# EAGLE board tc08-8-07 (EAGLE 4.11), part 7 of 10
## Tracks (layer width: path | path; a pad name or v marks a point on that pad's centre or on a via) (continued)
MKT\  (via drill 0.61)
  Top 0.254: v203.24,152.71 201.97,153.98 201.97,158.1 B13.T2 | v243.88,153.98 244.19,154.29 244.19,156.2 243.88,156.52 243.88,159.37 245.46,160.96 245.46,164.14 245.78,164.45 B10.R1 | v240.7,84.44 240.7,71.43 241.02,71.11 241.02,66.66 241.65,66.03 241.65,55.55 242.61,54.6 D10.H2 | v198.16,86.03 197.2,86.98 197.2,96.83 196.57,97.46 196.57,106.35 195.62,107.3 C14.N1 | v197.52,152.71 196.57,152.71 196.57,153.02 194.66,154.93 v194.66,156.52 | v160.69,157.15 159.1,157.15 159.1,139.69 162.28,136.51 162.28,120 v163.23,119.05
  Route15 0.254: v210.54,150.17 208.63,152.07 B13.V1
  Bottom 0.254: B13.V1 207.36,152.71 v203.24,152.71 202.92,152.39 202.92,151.12 200.38,151.12 198.79,152.71 v197.52,152.71 | v243.88,153.98 243.56,153.66 238.8,153.66 234.67,149.53 218.48,149.53 218.16,149.85 210.86,149.85 v210.54,150.17 | v240.7,84.44 240.38,84.76 229.59,84.76 229.27,84.44 225.78,84.44 224.51,85.71 213.4,85.71 212.76,85.08 212.13,85.08 210.86,86.35 198.47,86.35 v198.16,86.03 | v194.66,156.52 194.35,156.83 190.54,156.83 189.9,156.2 187.04,156.2 186.41,156.83 177.84,156.83 177.2,156.2 174.34,156.2 173.39,157.15 v160.69,157.15 | v163.23,119.05 163.55,118.73 168.95,118.73 178.47,109.21 185.77,109.21 188.31,106.67 193.71,106.67 194.66,107.62 C14.N1
MKTK  (via drill 0.61)
  Top 0.254: v65.12,235.26 67.03,237.16 67.03,241.92 v71.79,246.68 | v70.52,247.96 69.57,248.91 v69.57,256.21 | v90.84,260.97 91.79,261.93 91.79,265.42 v91.48,265.74 | v147.04,265.1 152.12,270.18 152.12,271.45 158.79,278.12 v168.63,278.12 | v176.57,275.9 177.84,275.9 179.11,274.62 183.23,274.62 v183.23,275.9 | v264.2,256.21 263.88,255.89 263.88,253.35 265.15,252.08 v266.74,252.08 | v264.83,239.7 264.83,235.57 A08.R2
  Route2 0.254: v62.27,237.8 64.81,235.26 v65.12,235.26 | v168.63,278.12 173.71,273.04 v176.57,275.9
  Route15 0.254: v131.16,264.15 133.7,264.15 v134.66,265.1 | v183.23,275.9 184.19,275.9 185.14,274.94 191.49,274.94 191.81,274.62 217.21,274.62 220.06,271.77 222.6,271.77 224.51,273.67 226.41,271.77 235.94,271.77 237.53,273.36 239.11,271.77 249.91,271.77 262.61,259.07 262.61,258.43 263.24,257.8 263.24,257.16 v264.2,256.21 | v266.74,252.08 266.74,244.78 263.24,241.29 v264.83,239.7
  Bottom 0.254: v62.27,237.8 59.41,237.8 A25.P1 | v70.52,247.96 v71.79,246.68 | v69.57,256.21 69.25,255.89 61.63,255.89 61,256.53 60.04,256.53 59.41,255.89 58.14,255.89 57.5,256.53 57.5,259.07 74.01,259.07 74.33,258.75 76.55,258.75 76.87,259.07 88.94,259.07 v90.84,260.97 | v91.48,265.74 91.79,265.42 128.62,265.42 129.89,264.15 v131.16,264.15 | v134.66,265.1 134.97,264.78 146.72,264.78 v147.04,265.1
MKTK\  (via drill 0.61)
  Top 0.254: v277.53,209.54 276.26,210.81 276.26,226.68 268.32,234.62 A08.P2 | B04.B1 v322.3,208.9 | v257.21,239.7 257.21,244.78 256.58,245.42 256.58,249.54 255.94,250.18 A09.K2
  Bottom 0.254: v322.3,208.9 321.98,209.22 277.85,209.22 v277.53,209.54 | v257.21,239.7 257.53,239.38 263.88,239.38 264.83,238.43 267.69,238.43 A08.P2
MOVE\  (via drill 0.61)
  Top 0.254: v279.44,52.06 279.12,51.74 279.12,23.16 279.75,22.53 279.75,19.67 280.39,19.04 280.39,10.15 280.71,9.83 v280.71,5.7 | v4.48,36.5 4.8,36.82 4.8,72.38 3.53,73.65 3.53,222.24 4.16,222.87 4.16,249.23 2.89,250.49 2.89,267.32 3.53,267.96 3.53,287.64 2.58,288.6 2.58,289.23 v5.12,291.77 | v269.28,294.94 258.8,294.94 258.8,276.53 v257.85,275.58
  Route2 0.254: v257.85,275.58 259.12,274.31 261.97,274.31 265.78,270.5 260.7,265.42 259.43,265.42 256.26,262.24 254.67,262.24 253.08,260.66 A09.F2
  Bottom 0.254: v279.44,52.06 280.07,52.69 285.47,52.69 285.47,57.77 284.83,58.41 284.52,58.41 284.52,62.85 D07.D1 | v280.71,5.7 261.34,5.7 260.07,4.43 231.81,4.43 229.91,6.34 223.87,6.34 223.24,5.7 35.28,5.7 v4.48,36.5 | v5.12,291.77 5.43,291.45 52.42,291.45 53.06,290.82 55.92,290.82 56.87,289.86 61.95,289.86 62.58,289.23 82.27,289.23 83.54,290.5 96.87,290.5 97.51,289.86 130.85,289.86 132.43,291.45 143.86,291.45 144.18,291.13 181.65,291.13 182.92,292.41 202.6,292.41 202.92,292.09 206.73,292.09 207.05,292.41 209.59,292.41 211.49,294.31 229.91,294.31 230.86,293.36 234.99,293.36 235.62,293.99 268.01,293.99 268.96,294.94 v269.28,294.94
MR00  (via drill 0.61)
  Top 0.254: v57.82,267 57.5,267.32 57.5,280.02 58.14,280.66 v58.14,292.09 | v139.42,296.22 139.42,278.12 139.1,277.8 139.1,273.99 139.74,273.36 139.74,264.78 139.42,264.47 139.42,237.48 140.37,236.52 140.37,232.71 140.05,232.4 140.05,207 139.74,206.68 139.74,206.05 v141.96,203.82 | v165.14,202.24 165.14,197.15 167.99,194.3 167.99,192.71 167.04,191.76 v167.04,191.44 | v188,192.71 187.68,192.39 187.68,187.31 | 187.68,187.31 187.68,181.92 v188.31,181.28 | v192.44,196.52 190.85,194.93 190.85,190.49 187.68,187.31
  Route2 0.254: v192.44,196.52 v198.47,202.55
  Route15 0.254: v188.31,181.28 191.49,178.11 191.49,175.56 191.81,175.25 B14.M2 | v261.02,184.46 271.82,173.66 271.82,173.02 276.26,168.58 280.39,168.58 B07.P2 | v249.27,183.18 248.96,183.18 246.73,185.41 237.53,185.41 237.21,185.73 236.26,185.73 229.27,192.71 226.73,192.71 v224.19,195.25 | v207.68,194.61 207.05,194.61 201.97,199.7 201.33,199.7 v198.47,202.55
  Bottom 0.254: v57.82,267 56.23,267 A25.D1 | v58.14,292.09 58.46,291.77 81.95,291.77 82.59,292.41 97.51,292.41 98.78,293.68 101.95,293.68 102.59,293.04 129.26,293.04 130.85,294.63 131.16,294.63 133.07,296.53 139.1,296.53 v139.42,296.22 | v141.96,203.82 143.86,201.92 164.82,201.92 v165.14,202.24 | v167.04,191.44 167.36,191.76 176.88,191.76 177.52,192.39 187.68,192.39 v188,192.71 | v261.02,184.46 259.43,182.87 249.59,182.87 v249.27,183.18 | v224.19,195.25 223.24,196.2 221.97,196.2 220.7,194.93 208,194.93 v207.68,194.61
MR00\  (via drill 0.61)
  Top 0.254: v282.61,175.56 282.61,174.3 279.12,170.8 279.12,166.68 278.17,165.72 B07.R2 | v294.36,177.15 v293.09,178.42 | v305.47,176.83 307.06,178.42 307.06,179.69 v308.33,180.96 | v328.97,193.03 328.65,193.34 v328.65,195.25 | v337.54,195.25 336.9,194.61 336.9,188.9 337.86,187.95 B03.H1
  Route2 0.254: v308.33,180.96 309.6,180.96 v315.63,186.99
  Bottom 0.254: v282.61,175.56 283.56,176.52 291.18,176.52 v293.09,178.42 | v294.36,177.15 294.99,176.52 305.15,176.52 v305.47,176.83 | v315.63,186.99 317.85,189.22 322.93,189.22 326.74,193.03 v328.97,193.03 | v328.65,195.25 328.97,195.57 337.22,195.57 v337.54,195.25
MR01  (via drill 0.61)
  Top 0.254: v6.39,252.4 7.02,251.77 7.02,251.13 7.34,250.81 7.34,180.64 6.7,180.01 6.7,178.74 7.34,178.11 7.34,77.14 6.7,76.5 6.7,75.24 7.97,73.97 7.97,4.75 v7.66,4.43 | v300.07,2.21 304.84,6.97 304.84,20.94 304.2,21.58 304.2,24.44 304.52,24.75 304.52,31.1 305.15,31.74 305.15,56.5 307.69,59.04 307.69,62.53 307.38,62.85 307.38,64.76 308.65,66.03 308.65,68.88 308.01,69.52 v308.01,75.87 | v281.34,76.19 281.66,76.5 281.66,88.89 v280.71,89.84 | v273.4,90.16 273.4,97.46 v273.09,97.78 | v280.71,101.27 280.71,104.13 C07.P2 280.71,105.4 v280.71,109.52 | v242.61,109.52 242.92,109.21 v242.92,106.67
  Route2 0.254: v278.17,98.73 v280.71,101.27
  Route15 0.254: v243.24,113.33 232.45,124.13 232.45,125.4 221.33,136.51 221.33,137.78 221.02,138.1 221.02,139.05 C12.B1 | v255.31,107.62 v252.77,105.08 | v280.71,109.52 v277.85,112.38
  Bottom 0.254: v6.39,252.4 15.59,261.61 47.98,261.61 48.61,262.24 57.19,262.24 58.14,263.19 A25.E1 | v7.66,4.43 7.97,4.12 8.61,4.12 8.93,3.8 9.88,3.8 11.15,2.53 228,2.53 228.64,3.16 229.27,3.16 230.54,1.89 261.66,1.89 262.93,3.16 263.56,3.16 265.47,1.26 299.12,1.26 v300.07,2.21 | v308.01,75.87 307.69,75.55 282.61,75.55 281.98,76.19 v281.34,76.19 | v280.71,89.84 280.39,90.16 v273.4,90.16 | v273.09,97.78 273.72,97.14 276.58,97.14 v278.17,98.73 | v243.24,113.33 241.65,111.75 241.65,109.52 v242.61,109.52 | v242.92,106.67 246.1,103.49 251.18,103.49 v252.77,105.08 | v255.31,107.62 257.53,109.84 264.2,109.84 264.83,110.48 267.05,110.48 267.69,109.84 275.31,109.84 v277.85,112.38
MR01\  (via drill 0.61)
  Top 0.254: v302.61,123.49 301.98,124.13 301.98,134.29 v302.61,134.93 | v254.04,129.21 255.62,127.62 255.62,125.72 254.35,124.45 254.35,122.54 255.94,120.96 v255.94,119.37
  Route2 0.254: v284.2,110.16 278.48,104.44 278.48,102.86 278.17,102.54 278.17,102.22 C07.R2 | v302.61,123.49 v293.72,114.61 | v302.61,134.93 302.93,134.93 306.42,138.42 306.42,139.05 309.6,142.23 310.23,142.23 312.14,144.13 313.73,144.13 320.39,150.8 320.39,153.02 320.71,153.34 320.71,154.29 324.52,158.1 324.52,159.05 336.27,170.8 336.27,172.39 337.86,173.98 B03.M1 | v217.21,171.44 210.86,177.79 210.86,178.11 203.55,185.41 203.55,187.95 204.82,189.22 198.79,195.25 198.79,199.38 B14.C1
  Route15 0.254: v217.21,171.44 217.21,170.49 221.97,165.72 221.97,159.37 230.22,151.12 230.22,150.8 230.86,150.17 231.81,150.17 242.29,139.69 243.56,139.69 v254.04,129.21 | v259.12,117.78 259.12,116.51 260.7,114.92 261.66,114.92 263.24,113.33 263.24,112.7 266.1,109.84 266.1,108.89 269.59,105.4 269.59,104.76 271.5,102.86 276.26,102.86 277.21,101.91 C07.R2
  Bottom 0.254: v284.2,110.16 284.52,109.84 288.96,109.84 v293.72,114.61 | v255.94,119.37 257.53,117.78 v259.12,117.78
N$1
  Bottom 0.254: B08.S2 268.96,162.23 269.91,163.18 289.28,163.18 290.23,162.23 293.09,162.23 B06.S2
N$2
  Top 0.254: C16.M2 166.41,111.75 166.41,116.83 C16.K2 | C16.N2 163.23,108.57 163.23,113.65 C16.L2 163.23,114.92 163.23,115.24 161.64,116.83 161.64,131.75 157.52,135.88 157.52,139.05 C17.B1
  Bottom 0.254: C16.K2 166.41,116.83 164.18,114.61 C16.L2
N$3  (via drill 0.61)
  Top 0.254: v230.54,166.04 230.54,162.55 B11.S2 | v239.43,175.56 239.11,175.88 239.11,176.52 238.48,177.15 238.48,188.27 v239.11,188.9 | v243.88,207.95 243.88,220.65 243.56,220.97 243.56,222.87 243.24,223.19 243.24,223.83 244.51,225.09 v244.51,226.05 | v233.72,230.49 233.72,234.3 A11.R1
  Route2 0.254: v230.54,166.04 236.89,172.39 236.89,173.02 v239.43,175.56 | v239.11,188.9 236.57,191.44 244.51,199.38 244.51,207.31 v243.88,207.95
  Route15 0.254: v244.51,226.05 v240.38,230.18
  Bottom 0.254: v240.38,230.18 240.07,230.49 v233.72,230.49
N$4
  Top 0.254: D13.S2 204.19,28.88 201.97,31.1 D13.R2
N$5  (via drill 0.61)
  Top 0.254: v15.91,149.85 15.59,150.17 15.59,209.54 12.42,212.71 12.42,246.05 15.59,249.23 15.59,274.31 v34.96,293.68 | v65.44,296.22 77.51,296.22 87.03,286.69 87.03,275.26 92.43,269.86 92.43,264.78 v93.38,263.83 | v159.42,261.29 162.6,261.29 162.91,261.61 166.41,261.61 166.41,257.8 A16.H2
  Route15 0.254: v160.69,89.21 156.56,85.08 151.48,90.16 150.21,90.16 v149.26,89.21
  Bottom 0.254: v160.69,89.21 162.91,89.21 C16.V2 | v149.26,89.21 146.09,89.21 145.13,90.16 62.58,90.16 13.05,139.69 13.05,149.85 v15.91,149.85 | v34.96,293.68 38.14,296.85 64.81,296.85 v65.44,296.22 | v93.38,263.83 98.14,259.07 152.12,259.07 154.66,261.61 159.1,261.61 v159.42,261.29
N$6
  Top 0.254: D12.C1 223.56,67.3 223.56,72.38 D12.A1 | D12.B1 220.38,69.2 220.38,64.12 D12.D1
  Bottom 0.254: D12.B1 221.33,70.16 223.56,72.38 D12.A1 | D13.F2 202.28,57.46 203.87,59.04 206.73,59.04 209.27,61.58 218.48,61.58 220.06,63.17 D12.D1
N$7
  Top 0.254: A12.P1 223.24,238.43 221.02,240.65 A12.N1 220.38,241.92 220.38,242.24 219.43,243.19 219.43,252.4 220.38,253.35 A12.J1
N$8
  Top 0.254: D17.F2 150.53,57.77 148.94,59.36 148.94,75.55 149.26,75.87 149.26,84.44 154.34,89.52 154.34,90.47 155.61,91.74 155.61,96.83 157.2,98.41 C17.R1
N$10  (via drill 0.61)
  Top 0.254: v233.72,141.27 233.08,141.91 v233.08,150.48 | v215.3,154.61 215.62,154.93 215.62,167.31 v215.3,167.63 | v223.56,171.12 223.56,173.98 B12.M1
  Route2 0.254: v221.02,168.58 v223.56,171.12
  Bottom 0.254: v233.72,141.27 234.67,141.27 234.67,139.69 236.26,138.1 236.26,137.15 C11.C1 | v233.08,150.48 232.76,150.17 223.56,150.17 222.29,151.43 221.65,151.43 221.33,151.12 218.79,151.12 v215.3,154.61 | v215.3,167.63 215.94,166.99 219.43,166.99 v221.02,168.58
N$11  (via drill 0.61)
  Top 0.254: v233.72,129.21 233.72,127.62 C11.F1 | v241.02,131.43 241.34,131.75 241.34,138.42 242.61,139.69 v242.61,140.64 | v245.78,141.27 245.46,141.59 245.46,150.48 v245.78,150.8 | v221.02,154.29 219.75,155.56 219.75,157.79 219.11,158.42 219.11,160.64 220.38,161.91 220.38,164.45 B12.R1
  Bottom 0.254: v233.72,129.21 235.94,131.43 v241.02,131.43 | v242.61,140.64 243.24,141.27 v245.78,141.27 | v245.78,150.8 244.83,151.75 244.83,156.83 241.34,156.83 239.43,154.93 237.84,154.93 237.21,154.29 225.78,154.29 225.46,154.61 224.83,154.61 224.51,154.29 v221.02,154.29
N$12
  Top 0.254: D17.E2 153.39,60.63 151.17,62.85 D17.D2
N$13
  Top 0.254: A14.K2 191.81,251.45 191.81,256.53 A14.H2 | B15.F1 182.92,191.12 183.87,192.08 183.87,208.58 183.23,209.22 183.23,220.02 187.04,223.83 187.04,248.91 187.68,249.54 187.68,252.4 188.63,253.35 A14.J2
  Bottom 0.254: A14.H2 191.81,256.53 189.58,254.3 A14.J2
N$14
  Top 0.254: A16.E2 166.09,263.83 163.87,266.05 A16.D2
N$15  (via drill 0.61)
  Top 0.254: v135.29,138.42 v135.29,140.96 | v113.07,142.55 112.43,143.18 v112.43,149.53 | v43.22,148.26 41.63,149.85 41.63,178.42 41.95,178.74 41.95,183.18 41.63,183.5 41.63,204.14 42.26,204.77 v42.26,214.62 | v17.82,223.83 16.23,223.83 16.23,235.57 16.55,235.89 16.55,240.33 16.23,240.65 16.23,273.67 v36.23,293.68 | v104.18,295.58 120.69,279.07 129.89,279.07 129.89,270.5 130.53,269.86 130.53,266.05 132.12,264.47 v132.12,262.56
  Route2 0.254: v113.07,142.55 v115.61,140.01
  Route15 0.254: v154.98,139.37 157.52,136.83 159.74,136.83 C17.C1
  Bottom 0.254: v154.98,139.37 153.39,140.96 v135.29,140.96 | v135.29,138.42 117.19,138.42 v115.61,140.01 | v112.43,149.53 111.8,148.89 81.95,148.89 80.68,147.62 58.77,147.62 58.14,148.26 v43.22,148.26 | v42.26,214.62 35.6,221.29 33.06,221.29 30.83,223.51 18.13,223.51 v17.82,223.83 | v36.23,293.68 36.55,293.99 52.74,293.99 53.06,294.31 64.17,294.31 64.49,293.99 81.32,293.99 82.27,294.94 97.19,294.94 97.83,295.58 v104.18,295.58 | v132.12,262.56 133.07,261.61 142.91,261.61 143.55,262.24 161.33,262.24 162.91,260.66 A16.F2
N$16  (via drill 0.61)
  Top 0.254: v152.12,209.54 152.12,139.05 151.8,138.74 151.8,134.61 151.17,133.97 C17.D2 | v178.79,209.54 178.47,209.86 178.47,224.46 178.15,224.78 178.15,241.29 180.69,243.83 180.69,261.61 181.33,262.24 181.33,265.1 182.28,266.05 A15.D1 183.23,267 185.46,269.23 A15.C1
  Bottom 0.254: v152.12,209.54 v178.79,209.54
N$17  (via drill 0.61)
  Top 0.254: v182.92,137.78 182.92,137.15 181.33,135.56 181.33,130.16 178.15,126.99 178.15,121.91 177.52,121.27 177.52,88.25 177.2,87.94 177.2,71.43 177.52,71.11 177.52,69.2 177.2,68.88 177.2,64.76 176.57,64.12 D15.D2 | v185.46,139.69 187.04,141.27 187.04,160.64 v188,161.59 | v192.44,171.12 190.85,169.53 190.85,166.36 192.12,165.09 B14.S2
  Bottom 0.254: v182.92,137.78 184.82,139.69 v185.46,139.69 | v188,161.59 191.49,161.59 B14.S2 | v192.44,171.12 194.66,171.12 B14.N1
N$18  (via drill 0.61)
  Top 0.254: v189.27,192.08 190.22,193.03 190.22,207 190.85,207.63 190.85,236.52 191.81,237.48 A14.P2 191.49,238.43 189.27,240.65 A14.N2 189.58,241.61 191.81,243.83 A14.M2
  Bottom 0.254: v189.27,192.08 188.95,191.76 177.84,191.76 176.88,190.8 B15.F2
N$19
  Top 0.254: A14.L2 189.58,247.96 194.03,247.96 194.03,250.81 198.16,254.94 198.16,256.53 A14.H1
N$20
  Top 0.254: A16.S2 166.09,232.08 163.87,234.3 A16.R2
N$21
  Top 0.254: A14.E2 191.49,263.83 189.27,266.05 A14.D2
N$22  (via drill 0.61)
  Top 0.254: v229.91,230.18 229.91,226.05 A11.U2
  Bottom 0.254: v229.91,230.18 220.38,230.18 220.06,229.86 197.52,229.86 197.2,230.18 194.98,230.18 194.66,229.86 190.54,229.86 189.58,228.9 A14.T2
N$23  (via drill 0.61)
  Top 0.254: v188.95,236.52 187.68,237.8 187.68,248.27 190.22,250.81 190.22,254.62 189.58,255.26 189.58,259.38 189.27,259.7 A14.F2
  Bottom 0.254: v188.95,236.52 189.27,236.21 225.78,236.21 227.68,238.11 A11.P2
N$24  (via drill 0.61)
  Top 0.254: v172.44,108.89 171.8,108.25 171.8,104.13 172.12,103.81 172.12,99.68 172.76,99.05 C16.S1 | v105.13,115.56 105.13,172.07 v106.72,173.66 | v163.23,174.3 166.41,177.47 166.41,180.33 B16.K2
  Route15 0.254: v172.44,108.89 172.44,109.21 v168.31,113.33
  Bottom 0.254: v168.31,113.33 167.99,113.02 131.16,113.02 128.62,115.56 v105.13,115.56 | v106.72,173.66 108.94,175.88 124.5,175.88 124.81,176.2 130.85,176.2 131.16,176.52 136.56,176.52 137.2,175.88 149.26,175.88 151.8,173.34 162.28,173.34 v163.23,174.3
N$25
  Top 0.254: A14.V2 188.63,222.87 187.68,223.83 187.68,233.35 188.63,234.3 A14.R2
N$26
  Bottom 0.254: A14.S2 192.76,231.45 197.84,231.45 A14.S1
N$27
  Top 0.254: D15.S2 179.11,29.2 177.52,30.78 177.52,33.32 176.57,34.28 176.57,37.45 D15.N2
N$28  (via drill 0.61)
  Top 0.254: v224.19,84.76 224.19,91.43 C12.U1 | v246.42,78.09 246.1,77.77 246.1,73.97 v246.42,73.65 | v245.78,61.9 246.42,61.27 246.42,58.72 247.37,57.77 247.37,53.96 244.83,51.42 244.83,42.21 245.78,41.26 v245.78,39.68 | v214.67,34.6 212.44,34.6 212.44,33.01 209.9,30.47 v209.9,17.45 | v129.89,17.45 127.35,19.99 127.35,99.68 127.67,100 127.67,103.81 127.35,104.13 127.35,121.59 v127.99,122.22 | v125.45,141.27 125.77,141.59 125.77,150.17 124.18,151.75 124.18,174.3 v125.13,175.25 | v127.35,177.47 v127.35,182.23 | v168.95,181.92 168.63,182.23 168.63,185.41 v170.22,186.99
  Route2 0.254: v246.42,73.65 245.46,72.69 245.46,71.11 244.83,70.47 244.83,62.85 v245.78,61.9 | v125.13,175.25 v127.35,177.47
  Route15 0.254: v193.08,189.54 194.35,189.54 197.84,186.04 203.24,186.04 205.78,183.5 206.73,183.5 207.36,182.87 208.63,182.87 209.27,182.23 209.27,180.96 210.54,179.69 212.13,179.69 213.71,178.11 B12.L2
  Bottom 0.254: v224.19,84.76 224.19,84.13 226.1,82.22 226.1,80.32 244.19,80.32 v246.42,78.09 | v245.78,39.68 244.83,38.72 242.29,38.72 240.38,36.82 239.11,36.82 238.16,37.77 234.99,37.77 234.03,36.82 217.21,36.82 214.98,34.6 v214.67,34.6 | v209.9,17.45 209.59,17.13 182.28,17.13 181.65,17.77 177.84,17.77 177.2,17.13 130.21,17.13 v129.89,17.45 | v127.99,122.22 121.32,128.89 115.29,128.89 114.65,129.53 114.65,140.96 125.13,140.96 v125.45,141.27 | v127.35,182.23 168.63,182.23 v168.95,181.92 | v170.22,186.99 172.44,189.22 176.88,189.22 177.52,189.85 181.33,189.85 181.96,189.22 192.76,189.22 v193.08,189.54
N$29
  Top 0.254: B16.D2 163.87,196.2 166.09,193.98 B16.E2
N$30  (via drill 0.61)
  Top 0.254: v153.39,119.37 152.75,120 152.75,128.58 153.71,129.53 C17.E2 | v120.69,120.96 120.37,121.27 v120.37,188.58
  Bottom 0.254: v153.39,119.37 152.75,118.73 122.91,118.73 v120.69,120.96 | v120.37,188.58 158.47,188.58 160.06,190.17 162.91,190.17 B16.F2
N$31  (via drill 0.61)
  Top 0.254: v153.71,259.38 148.94,254.62 148.94,221.29 149.26,220.97 149.26,211.44 148.94,211.12 148.94,129.21 150.53,127.62 C17.F2
  Bottom 0.254: v153.71,259.38 154.02,259.07 165.45,259.07 168.31,261.93 174.66,261.93 175.93,263.19 | 175.93,263.19 178.79,263.19 A15.E2 | 175.93,263.19 175.93,266.05 A15.D2
N$32  (via drill 0.61)
  Top 0.254: v132.12,115.88 130.53,117.46 130.53,149.21 131.16,149.85 v131.16,150.17 | v181.01,155.24 v181.01,161.59
  Bottom 0.254: v132.12,115.88 132.43,115.56 151.48,115.56 152.75,114.29 C17.L1 | v131.16,150.17 137.51,150.17 138.15,150.8 144.82,150.8 145.45,150.17 156.88,150.17 160.37,153.66 166.41,153.66 167.04,154.29 176.57,154.29 177.2,154.93 178.15,154.93 178.79,154.29 180.06,154.29 v181.01,155.24 | v181.01,161.59 185.14,161.59 B15.S1
N$33  (via drill 0.61)
  Top 0.254: v261.34,164.77 263.24,166.68 263.24,183.5 v262.93,183.82 | v252.77,192.08 250.86,193.98 v250.86,196.2 | v256.58,197.47 257.53,198.43 v257.53,205.41 | v264.2,206.68 264.2,221.29 263.88,221.6 263.88,222.87 266.1,225.09 267.69,225.09 A08.U2
  Route2 0.254: v259.75,163.18 v261.34,164.77
  Bottom 0.254: v259.75,163.18 250.86,163.18 249.91,162.23 B10.S1 | v262.93,183.82 262.93,186.36 263.24,186.68 263.24,189.54 261.66,189.54 261.34,189.85 260.07,189.85 259.43,189.22 251.81,189.22 251.18,189.85 251.18,192.08 v252.77,192.08 | v250.86,196.2 251.5,195.57 254.67,195.57 v256.58,197.47 | v257.53,205.41 257.85,205.09 262.61,205.09 v264.2,206.68
N$34  (via drill 0.61)
  Top 0.254: v146.4,27.29 145.77,27.93 145.77,73.33 148.63,76.19 148.63,84.76 152.75,88.89 152.75,96.83 153.71,97.78 C17.S2
  Bottom 0.254: v146.4,27.29 149.58,27.29 149.9,26.98 161.64,26.98 162.91,25.71 D16.T2
N$35  (via drill 0.61)
  Top 0.254: v283.25,239.38 282.93,239.7 282.93,249.54 v283.25,249.86
  Route2 0.254: v248.96,108.89 245.15,105.08 243.56,105.08 C10.P2 | v202.6,163.5 203.24,163.5 207.36,167.63 208.63,167.63 210.54,169.53 216.57,169.53 220.7,173.66 220.7,175.88 221.97,177.15 221.97,192.39 221.02,193.34 221.97,194.3 222.6,194.3 223.24,194.93 223.24,195.57 v224.19,196.52 | v236.89,189.85 239.11,187.63 241.02,189.54 241.02,192.08 239.75,193.34 240.7,194.3 241.65,194.3 242.29,194.93 243.24,194.93 244.83,196.52 244.83,197.47 255.31,207.95 257.85,207.95 260.7,210.81 260.7,213.67 264.2,217.16 264.2,219.38 274.04,229.22 274.04,229.54 274.99,230.49 275.31,230.49 282.29,237.48 282.29,238.43 v283.25,239.38 | v271.82,256.21 271.82,257.48 269.28,260.02 268.96,259.7 267.69,259.7 263.88,263.51 262.61,262.24 261.02,262.24 259.43,260.66 A09.F1
  Route15 0.254: v248.96,108.89 245.46,112.38 245.46,113.02 244.83,113.65 244.83,119.05 244.19,119.69 244.19,120.64 241.65,123.18 241.65,123.81 241.02,124.45 240.38,124.45 225.78,139.05 225.78,143.81 217.21,152.39 216.25,152.39 207.36,161.28 207.05,161.28 206.41,161.91 206.41,162.86 204.82,164.45 204.19,164.45 202.92,163.18 v202.6,163.5 | v224.19,196.52 225.46,196.52 226.41,195.57 230.22,195.57 231.49,194.3 231.49,193.66 233.08,192.08 234.67,192.08 v236.89,189.85
  Bottom 0.254: v283.25,249.86 282.93,249.54 279.44,249.54 272.77,256.21 v271.82,256.21
N$36  (via drill 0.61)
  Top 0.254: v198.79,109.21 198.79,105.4 C14.P1 | v203.87,109.52 203.55,109.84 203.55,133.34 204.19,133.97 204.19,134.61 203.55,135.24 201.97,135.24 201.97,133.97 C13.D2
  Bottom 0.254: v198.79,109.21 199.11,109.52 v203.87,109.52
N$37
  Top 0.254: B16.S2 166.09,162.23 163.87,164.45 B16.R2
N$38
  Top 0.254: C15.H1 186.09,124.45 187.04,125.4 187.04,133.02 186.09,133.97 186.09,135.88 C15.C1
N$39
  Top 0.254: C15.J1 182.28,121.27 182.28,126.35 C15.F1
N$40
  Top 0.254: D14.V2 189.27,19.67 190.22,20.62 190.22,36.18 191.81,37.77 191.81,40.63 D14.M2
N$41
  Top 0.254: D14.V1 195.62,19.67 197.2,21.26 197.2,30.78 198.16,31.74 198.16,34.28 D14.P1
N$42
  Top 0.254: C11.L1 234.03,114.61 236.26,116.83 C11.K1
N$43
  Top 0.254: A12.T2 214.67,229.22 215.62,230.18 215.62,239.7 214.67,240.65 A12.N2
N$44  (via drill 0.61)
  Top 0.254: v239.43,115.88 v239.43,119.05 | v241.97,126.99 241.65,127.3 241.65,130.8 242.29,131.43 v242.29,133.97 | v240.38,134.93 240.7,135.24 240.7,138.74 241.02,139.05 v241.02,143.5 | v241.02,146.04 v241.02,148.89 | v217.84,148.89 217.84,154.93 B12.U2
  Route2 0.254: v236.89,120.96 239.75,123.81 239.75,124.77 v241.97,126.99 | v241.02,143.5 v241.02,146.04
  Bottom 0.254: v239.43,115.88 234.03,110.48 233.72,110.48 233.72,108.57 C11.N1 | v239.43,119.05 237.53,120.96 v236.89,120.96 | v242.29,133.97 241.34,134.93 v240.38,134.93 | v241.02,148.89 v217.84,148.89
N$45
  Top 0.254: A12.U2 217.21,226.05 217.21,231.13 A12.S2
N$46
  Bottom 0.254: A10.K1 249.91,251.13 251.5,252.72 257.21,252.72 258.16,253.67 A09.J1
N$47  (via drill 0.61)
  Top 0.254: v204.82,138.42 203.24,140.01 v203.24,150.17 | v204.51,163.5 205.46,164.45 205.46,166.99 v206.41,167.95 | v201.97,167.95 197.2,172.71 197.2,189.22 200.06,192.08 v200.7,192.08
  Route15 0.254: v208.63,156.2 203.55,161.28 203.55,162.55 v204.51,163.5 | v200.7,192.08 202.6,193.98 v202.92,193.66 | v220.38,192.71 220.7,192.71 223.87,189.54 224.51,189.54 v226.73,187.31
  Bottom 0.254: v204.82,138.42 206.41,136.83 210.54,136.83 C13.C1 | v203.24,150.17 204.19,151.12 208.63,151.12 209.59,152.07 209.59,156.2 v208.63,156.2 | v206.41,167.95 205.46,166.99 202.92,166.99 v201.97,167.95 | v202.92,193.66 204.19,192.39 220.06,192.39 v220.38,192.71 | v226.73,187.31 B11.H2
N$48  (via drill 0.61)
  Top 0.254: v236.89,106.99 236.89,105.4 C11.P1 | v240.07,109.52 v240.07,112.7 | v248.96,119.05 249.27,119.37 249.27,121.91 v249.59,122.22 | v231.18,144.77 v231.18,151.12 | v224.19,151.12 224.19,153.98 225.14,154.93 225.14,156.2 224.51,156.83 224.51,161.59 B12.S1
  Route15 0.254: v249.59,122.22 251.5,124.13 248.64,126.99 248.64,128.89 248,129.53 248,133.97 v243.88,138.1 | v236.26,140.01 231.49,144.77 v231.18,144.77
  Bottom 0.254: v236.89,106.99 237.21,106.67 240.38,106.67 241.02,107.3 241.02,109.52 v240.07,109.52 | v240.07,112.7 242.92,115.56 245.46,115.56 v248.96,119.05 | v243.88,138.1 243.56,138.42 238.48,138.42 236.89,140.01 v236.26,140.01 | v231.18,151.12 v224.19,151.12
N$49  (via drill 0.61)
  Top 0.254: v226.73,179.37 228.32,180.96 228.32,188.58 229.91,190.17 229.91,193.03 B11.E2
  Bottom 0.254: v226.73,179.37 222.6,179.37 221.33,178.11 B12.L1
N$50  (via drill 0.61)
  Top 0.254: v184.5,86.03 184.5,99.05 185.46,100 185.46,104.13 C15.P1 | v210.54,85.39 210.22,85.71 210.22,91.11 209.9,91.43 v209.9,97.14
  Bottom 0.254: v184.5,86.03 184.82,86.35 196.57,86.35 197.84,85.08 200.38,85.08 201.01,85.71 210.22,85.71 v210.54,85.39 | v209.9,97.14 212.76,97.14 213.71,98.1 216.89,98.1 C12.S2
N$51  (via drill 0.61)
  Top 0.254: v221.97,150.48 221.97,132.7 221.33,132.07 221.33,127.94 221.02,127.62 C12.F1
  Bottom 0.254: v221.97,150.48 216.57,150.48 214.98,152.07 B12.V2
N$52  (via drill 0.61)
  Top 0.254: v236.26,115.24 236.26,114.29 235.3,113.33 235.3,104.13 235.62,103.81 235.62,99.68 236.26,99.05 C11.S1 | v245.78,122.22 v245.78,124.13 | v223.56,122.22 222.6,123.18 222.6,128.58 223.56,129.53 C12.E1
  Bottom 0.254: v236.26,115.24 239.11,118.1 239.75,118.1 241.97,120.32 241.97,121.27 244.83,121.27 v245.78,122.22 | v245.78,124.13 245.46,123.81 244.83,123.81 243.56,122.54 227.37,122.54 226.73,123.18 225.14,123.18 224.19,122.22 v223.56,122.22
N$53
  Top 0.254: C15.R1 182.28,102.22 182.28,107.3 C15.N1
N$54  (via drill 0.61)
  Top 0.254: C12.H1 v223.87,126.99
  Bottom 0.254: v223.87,126.99 C11.F2
N$55
  Bottom 0.254: B12.E1 224.51,193.98 226.73,196.2 B11.D2
N$56
  Bottom 0.254: B11.F2 227.37,191.12 227.37,194.93 228.32,194.93 229.91,196.52 232.76,196.52 B11.D1
N$58  (via drill 0.61)
  Top 0.254: v280.71,164.77 279.75,165.72 279.75,168.9 v281.66,170.8 | v266.1,187.95 266.42,188.27 266.42,193.66 263.88,196.2 263.88,204.77 263.24,205.41 263.24,216.21 262.29,217.16 262.29,220.33 262.61,220.65 262.61,222.55 v261.66,223.51 | v259.75,224.46 v258.16,226.05 | v233.72,224.46 233.72,222.87 A11.V1
  Route2 0.254: v271.5,154.61 273.4,156.52 273.4,157.47 v280.71,164.77
  Route15 0.254: v281.66,170.8 272.77,179.69 272.77,180.64 v268.64,184.77
  Bottom 0.254: v271.5,154.61 271.18,154.29 267.37,154.29 265.78,152.71 B08.V2 | v268.64,184.77 268.01,185.41 267.37,185.41 266.1,186.68 v266.1,187.95 | v261.66,223.51 260.7,224.46 v259.75,224.46 | v258.16,226.05 256.26,224.14 244.83,224.14 244.51,224.46 243.88,224.46 243.56,224.14 234.03,224.14 v233.72,224.46
N$59
  Bottom 0.254: C13.V1 208.63,88.57 209.59,87.62 221.65,87.62 222.92,88.89 C11.V2
N$60  (via drill 0.61)
  Top 0.254: v197.84,82.86 196.89,81.9 196.89,72.06 197.2,71.74 197.2,64.44 v197.84,63.81 | v125.13,65.08 123.54,66.66 123.54,76.19 123.86,76.5 123.86,85.08 121.32,87.62 121.32,91.11 117.19,95.24 117.19,133.34 118.46,134.61 118.46,138.42 117.83,139.05 117.83,167.95 117.19,168.58 v117.19,182.23
  Route2 0.254: v197.84,82.86 206.41,91.43 207.05,91.43 207.68,92.06 207.68,92.38 219.75,104.44 219.75,106.35 220.38,106.99 220.38,107.3 C12.N1
  Route15 0.254: v199.43,183.5 200.38,183.5 201.01,182.87 203.55,182.87 203.87,182.55 206.73,182.55 207.05,182.23 208,182.23 v208.32,181.92
  Bottom 0.254: v197.84,63.81 196.57,65.08 187.68,65.08 186.73,64.12 183.87,64.12 183.23,64.76 174.66,64.76 174.03,64.12 171.17,64.12 170.53,64.76 161.96,64.76 161.33,64.12 158.47,64.12 157.83,64.76 149.26,64.76 148.63,64.12 145.77,64.12 144.82,65.08 v125.13,65.08 | v117.19,182.23 117.83,182.87 120.37,182.87 122.91,185.41 160.37,185.41 162.91,182.87 198.79,182.87 v199.43,183.5 | v208.32,181.92 208.63,182.23 215.62,182.23 216.89,183.5 217.52,183.5 218.16,182.87 218.16,181.6 217.84,181.6 B12.K2
N$61  (via drill 0.61)
  Top 0.254: v214.67,75.24 v214.67,83.49 | v217.52,74.92 219.43,73.01 219.43,61.58 v219.75,61.27 | v208.32,59.36 207.36,60.31 v207.36,60.95 | v125.77,66.98 126.72,67.93 126.72,82.22 v126.4,82.54 | v101.32,85.71 v101.32,160.96 | v136.56,161.59 136.24,161.91 136.24,170.17 v135.29,171.12 | v144.18,174.93 145.77,176.52 v145.77,192.71 | v197.84,195.89 197.2,195.25 197.2,192.08 v197.84,191.44 | v217.21,178.11 217.21,175.25 B12.M2
  Route2 0.254: v214.67,83.49 219.75,88.57 220.06,88.57 C12.V1
  Route15 0.254: v197.84,191.44 197.84,191.12 199.43,189.54 200.7,189.54 204.19,186.04 206.73,186.04 208,187.31 v217.21,178.11
  Bottom 0.254: v214.67,75.24 214.98,74.92 v217.52,74.92 | v219.75,61.27 219.75,59.04 208.63,59.04 v208.32,59.36 | v207.36,60.95 206.73,61.58 196.25,61.58 195.3,60.63 193.71,60.63 192.76,61.58 136.56,61.58 135.93,62.22 124.81,62.22 122.91,64.12 122.91,65.39 124.5,66.98 v125.77,66.98 | v126.4,82.54 122.91,86.03 115.61,86.03 115.29,85.71 v101.32,85.71 | v101.32,160.96 101.64,160.64 135.61,160.64 v136.56,161.59 | v135.29,171.12 137.51,173.34 142.59,173.34 v144.18,174.93 | v145.77,192.71 146.09,192.39 168.63,192.39 171.8,195.57 177.52,195.57 177.84,195.89 181.65,195.89 181.96,195.57 197.52,195.57 v197.84,195.89
N$62
  Top 0.254: B12.N2 214.67,172.07 215.62,173.02 215.62,182.55 214.67,183.5 B12.J2
N$63  (via drill 0.61)
  Top 0.254: v198.16,178.74 199.74,177.15 199.74,173.66 201.33,172.07 B13.N2
  Bottom 0.254: v198.16,178.74 197.2,179.69 187.36,179.69 186.41,180.64 B15.K1
N$64  (via drill 0.61)
  Top 0.254: B10.D1 246.73,197.15 248.96,199.38 B10.C1 248.96,200.65 248.96,202.24 246.73,204.46 v246.73,217.16 | v209.59,247.32 209.27,247 209.27,227.32 v209.59,227 | v221.65,226.36 221.97,226.05 221.97,224.14 223.87,222.24 223.87,219.7 224.83,218.74 v224.83,217.48
  Bottom 0.254: v209.59,247.32 212.13,249.86 216.25,249.86 216.89,250.49 A12.K2 | v209.59,227 209.9,226.68 221.33,226.68 v221.65,226.36 | v224.83,217.48 225.46,218.11 245.78,218.11 v246.73,217.16
N$65  (via drill 0.61)
  Top 0.254: C11.T2 v227.05,98.41
  Bottom 0.254: v227.05,98.41 C11.S2
N$66  (via drill 0.61)
  Top 0.254: v215.3,288.91 215.62,288.6 215.62,261.93 214.67,260.97 A12.F2 | v271.18,287.96 276.58,282.56 276.58,231.76 279.12,229.22 279.12,207.31 278.8,207 278.8,206.68 v277.85,205.73
  Bottom 0.254: B10.B1 246.42,203.82 248.64,206.05 B10.A1 249.91,206.05 251.18,204.77 255.94,204.77 256.26,204.46 263.24,204.46 263.56,204.77 276.9,204.77 v277.85,205.73 | v215.3,288.91 215.62,288.6 217.84,288.6 218.79,287.64 230.22,287.64 230.86,288.28 237.53,288.28 238.16,288.91 270.23,288.91 v271.18,287.96
N$67  (via drill 0.61)
  Top 0.254: v187.36,33.32 187.68,33.64 187.68,49.2 188.63,50.15 D14.J2
  Bottom 0.254: v187.36,33.32 187.68,33.01 236.57,33.01 237.84,34.28 241.97,34.28 242.29,34.6 D10.P2
N$68  (via drill 0.61)
  Top 0.254: v194.98,61.58 196.57,60 196.57,56.18 198.16,54.6 D14.H1
  Bottom 0.254: v194.98,61.58 193.39,63.17 189.58,63.17 D14.D2
N$69
  Top 0.254: D14.C1 198.16,67.3 198.16,72.38 D14.A1
N$70  (via drill 0.61)
  Top 0.254: v231.18,157.15 231.18,160.96 231.49,161.28 231.49,168.9 230.54,169.85 v230.54,170.8 | v239.43,173.66 240.07,174.3 240.07,174.93 241.02,175.88 v241.02,193.34
  Bottom 0.254: v231.18,157.15 234.67,157.15 235.94,155.88 B11.U1 | v230.54,170.8 231.18,170.17 235.94,170.17 v239.43,173.66 | v241.02,193.34 237.21,193.34 B11.E1
N$71  (via drill 0.61)
  Top 0.254: v135.29,133.65 133.7,135.24 133.7,146.04 134.02,146.36 134.02,153.66 133.07,154.61 133.07,161.59 v132.75,161.91
  Bottom 0.254: v135.29,133.65 137.51,131.43 149.9,131.43 152.44,128.89 154.98,128.89 156.56,127.3 C17.F1 | v132.75,161.91 134.66,163.82 140.37,163.82 143.23,166.68 159.42,166.68 159.74,166.99 167.36,166.99 171.17,170.8 174.98,170.8 175.61,170.17 179.42,170.17 180.38,171.12 181.96,171.12 B15.N1
N$72  (via drill 0.61)
  Top 0.254: v233.72,185.73 234.67,184.77 234.67,173.02 233.72,172.07 B11.N1
  Bottom 0.254: v233.72,185.73 234.99,186.99 235.94,186.99 B11.H1
N$73
  Bottom 0.254: B09.N2 253.08,171.76 257.21,171.76 258.16,172.71 266.1,172.71 267.37,171.44 B08.N1
N$76  (via drill 0.61)
  Top 0.254: v181.01,110.8 180.69,110.48 180.69,100 179.74,99.05 C15.S2
  Bottom 0.254: v181.01,110.8 184.19,113.97 188.31,113.97 C14.L2
N$77
  Bottom 0.254: B11.J1 234.03,184.46 235.62,186.04 243.56,186.04 245.78,188.27 245.78,189.85 B10.F1
N$78  (via drill 0.61)
  Top 0.254: v160.69,127.94 161.01,127.62 161.01,124.77 160.69,124.45 C17.H1
  Route2 0.254: v166.72,127.3 172.44,133.02 172.44,133.97 181.96,143.5 181.96,143.81 182.6,144.45 183.87,144.45 192.44,153.02 194.03,153.02 197.84,156.83 203.24,156.83 211.17,164.77 211.17,165.09 211.81,165.72 213.08,165.72 213.71,166.36 217.52,166.36 226.41,175.25 227.68,175.25 v233.08,180.64
  Bottom 0.254: v160.69,127.94 161.01,128.26 165.77,128.26 v166.72,127.3 | v233.08,180.64 234.67,182.23 246.42,182.23 247.37,181.28 248.64,181.28 B10.K1
N$79
  Bottom 0.254: C14.N2 189.58,108.25 190.54,109.21 196.57,109.21 197.52,108.25 201.01,108.25 C13.N2
N$81  (via drill 0.61)
  Top 0.254: v206.41,130.16 206.09,129.84 206.09,112.7 205.14,111.75 C13.M2
  Bottom 0.254: v206.41,130.16 207.05,130.8 209.9,130.8 211.17,132.07 216.25,132.07 217.21,133.02 220.06,133.02 C12.D1
N$82  (via drill 0.61)
  Top 0.254: v104.18,121.91 104.49,122.22 v104.49,191.76 | v181.65,186.68 181.33,186.36 181.33,182.87 v182.92,181.28 | v229.59,147.94 230.22,148.58 230.22,151.43 v231.18,152.39
  Route15 0.254: v182.92,181.28 v189.9,174.3 | v199.74,171.44 223.24,147.94 v223.56,147.94
  Bottom 0.254: v104.18,121.91 121,121.91 123.54,119.37 151.48,119.37 152.44,120.32 156.56,120.32 C17.J1 | v104.49,191.76 124.81,191.76 125.13,192.08 127.35,192.08 127.99,191.44 130.85,191.44 131.16,191.76 165.45,191.76 169.26,187.95 169.26,186.04 181.01,186.04 v181.65,186.68 | v189.9,174.3 191.49,172.71 198.47,172.71 v199.74,171.44 | v223.56,147.94 v229.59,147.94 | v231.18,152.39 B11.V1
N$83
  Top 0.254: A09.L1 259.12,248.27 260.7,249.86 260.7,253.99 263.88,257.16 263.88,260.97 266.1,263.19 267.69,263.19 A08.E2
N$84
  Top 0.254: A10.D1 246.73,267 248.96,269.23 A10.C1
N$85  (via drill 0.61)
  Top 0.254: v180.69,177.47 180.69,173.98 179.42,172.71 B15.P2 | v176.57,187.31 176.88,187.63 176.88,189.22 177.52,189.85 177.52,193.98 v176.88,194.61 | A10.B1 245.78,272.4 245.15,271.77 245.15,267.64 244.83,267.32 244.83,261.93 245.78,260.97 A10.F1
  Route2 0.254: v176.57,181.28 176.57,182.55 177.52,183.5 177.52,186.36 v176.57,187.31 | v176.88,194.61 176.88,195.57 183.87,202.55 183.87,207.95 185.14,209.22 185.14,213.35 192.76,220.97 192.76,221.6 v198.79,227.64 | v214.67,238.11 215.62,238.11 216.89,239.38 221.97,239.38 225.14,242.56 225.14,243.19 230.22,248.27 230.86,248.27 232.76,250.18 234.03,250.18 242.29,258.43 243.88,258.43 245.46,260.02 A10.F1
  Route15 0.254: v198.79,227.64 205.14,233.99 205.78,233.35 208.63,233.35 214.03,238.75 v214.67,238.11
  Bottom 0.254: v180.69,177.47 176.88,181.28 v176.57,181.28
N$86  (via drill 0.61)
  Top 0.254: v178.15,194.93 178.15,193.03 178.79,192.39 178.79,188.58 178.15,187.95 178.15,163.5 179.11,162.55 B15.S2 | v218.16,197.47 219.43,198.74 219.43,203.82 v221.02,205.41 | v228.95,205.09 228.64,204.77 v228.64,197.47 | v230.54,189.54 228.95,187.95 228.95,184.77 v229.59,184.14
  Route2 0.254: v229.59,179.37 228.95,179.37 227.68,178.11 B11.L2
  Bottom 0.254: v178.15,194.93 201.01,194.93 201.65,195.57 202.6,195.57 205.14,198.11 209.59,198.11 210.22,197.47 213.08,197.47 213.71,198.11 215.62,198.11 216.25,197.47 v218.16,197.47 | v221.02,205.41 221.33,205.09 v228.95,205.09 | v228.64,197.47 228.64,196.2 228.32,196.2 227.68,195.57 227.05,195.57 225.78,194.3 225.78,189.22 230.22,189.22 v230.54,189.54 | v229.59,184.14 229.59,183.5 228.95,182.87 228.95,179.69 229.27,179.69 v229.59,179.37
N$88
  Top 0.254: D17.S2 153.39,28.88 151.17,31.1 D17.R2
N$91
  Bottom 0.254: B09.R1 259.43,164.77 261.02,163.18 264.51,163.18 267.05,160.64 270.86,160.64 272.13,161.91 B08.S1
N$92  (via drill 0.61)
  Top 0.254: v253.72,179.37 253.72,188.9 252.77,189.85 B09.F2
  Bottom 0.254: v253.72,179.37 254.04,179.06 269.59,179.06 271.18,180.64 274.04,180.64 B08.K1
N$93
  Top 0.254: D08.C1 274.36,66.03 272.13,63.81 D08.D1
  Bottom 0.254: D09.E1 262.61,60.63 264.2,62.22 269.91,62.22 270.86,63.17 D08.D1
N$94
  Bottom 0.254: D09.J2 253.08,51.1 254.04,52.06 257.21,52.06 257.85,52.69 258.8,52.69 262.93,56.82 264.51,56.82 D08.F2 265.78,57.46 268.01,59.68 D08.E2
N$95
  Bottom 0.254: D09.L1 259.43,44.75 260.39,45.71 272.45,45.71 274.04,47.29 D08.K1 274.04,47.93 271.82,50.15 D08.J1
N$96
  Bottom 0.254: D09.S1 262.61,28.88 263.56,29.83 266.42,29.83 268.32,31.74 D08.R1 272.13,32.06 274.36,34.28 D08.P1
N$97  (via drill 0.61)
  Top 0.254: v274.67,197.15 B08.C1
  Bottom 0.254: v274.67,197.15 274.04,197.15 273.09,198.11 264.51,198.11 263.88,197.47 259.75,197.47 259.43,197.15 B09.D1
N$99
  Top 0.254: D08.T2 265.47,24.75 267.69,22.53 D08.U2
  Bottom 0.254: D09.V2 253.08,19.35 254.04,20.31 263.24,20.31 265.15,22.21 D08.U2
N$100
  Bottom 0.254: D09.P2 256.26,35.23 257.85,36.82 261.02,36.82 261.97,37.77 264.51,37.77 D08.N2 265.78,38.4 268.01,40.63 D08.M2
N$101  (via drill 0.61)
  Top 0.254: D08.S2 268.01,29.2 266.42,30.78 266.42,42.85 265.47,43.8 D08.L2 264.83,45.07 263.88,46.03 263.88,61.9 264.83,62.85 D08.D2 | v166.72,24.12 165.45,25.39 165.45,31.74 162.28,34.91 162.28,54.92 159.1,58.09 159.1,73.65 160.06,74.6 160.06,76.5 159.74,76.82 159.74,91.11 160.06,91.43 C17.U1 | v242.92,20.31 v248.96,20.31
  Route15 0.254: v208.95,22.85 214.35,28.25 217.21,25.39 217.84,25.39 221.33,21.89 222.29,21.89 223.24,20.94 224.51,20.94 v226.73,23.16 | v235.62,19.35 v233.08,21.89 | v261.66,23.8 v265.78,27.93
  Bottom 0.254: v166.72,24.12 167.36,23.48 174.66,23.48 175.3,22.85 178.15,22.85 179.11,23.8 187.04,23.8 188,22.85 190.85,22.85 191.49,23.48 200.06,23.48 200.7,22.85 203.55,22.85 204.19,23.48 206.09,23.48 206.73,22.85 v208.95,22.85 | v226.73,23.16 227.05,23.48 231.49,23.48 v233.08,21.89 | v235.62,19.35 235.94,19.67 238.48,19.67 239.11,20.31 v242.92,20.31 | v248.96,20.31 249.59,20.94 258.8,20.94 v261.66,23.8 | v265.78,27.93 266.1,28.25 267.69,28.25 D08.S2
N$103  (via drill 0.61)
  Top 0.254: 270.23,52.38 270.23,39.68 271.18,38.72 D08.N1 | 270.23,52.38 271.5,53.64 274.04,53.64 D08.H1 | 270.23,52.38 270.23,64.12 270.55,64.44 270.55,68.57 271.18,69.2 D08.B1 272.13,70.16 273.72,70.16 276.58,73.01 276.58,86.98 v275.94,87.62 | v151.8,91.74 152.12,92.06 152.12,106.35 151.17,107.3 C17.N2
  Bottom 0.254: v151.8,91.74 152.75,90.79 234.99,90.79 235.62,90.16 241.34,90.16 244.19,87.3 275.63,87.3 v275.94,87.62
N$104
  Bottom 0.254: C09.N2 253.08,108.25 254.67,109.84 256.26,109.84 264.83,118.41 264.83,120 C08.J2
N$105  (via drill 0.61)
  Top 0.254: v237.84,265.1 237.84,274.62 236.89,275.58 A11.A1
  Bottom 0.254: v237.84,265.1 238.16,264.78 260.39,264.78 261.34,263.83 A09.E1
N$106  (via drill 0.61)
  Top 0.254: v252.45,271.13 253.72,269.86 253.72,263.51 254.99,262.24 254.99,258.11 255.31,257.8 A09.H2
  Bottom 0.254: v252.45,271.13 243.56,271.13 242.92,271.77 237.84,271.77 236.89,272.72 234.03,272.72 A11.B1
N$107  (via drill 0.61)
  Top 0.254: v255.62,246.05 254.99,246.68 254.99,248.59 252.77,250.81 252.77,253.35 A09.J2
  Bottom 0.254: v255.62,246.05 263.56,246.05 264.51,245.1 267.37,245.1 267.69,244.78 A08.M2
N$108  (via drill 0.61)
  Top 0.254: v130.53,109.21 129.89,108.57 v129.89,76.82 | v150.53,76.82 151.8,76.82 152.44,76.19 157.2,76.19 v157.2,76.82 | v165.77,77.77 165.77,76.19 166.41,75.55 173.71,75.55 v173.71,76.82 | v220.38,92.38 221.33,93.33 221.33,93.97 222.6,95.24 v222.6,96.83
  Route2 0.254: v216.89,88.57 216.89,88.89 v220.38,92.38 | v222.6,96.83 222.6,99.05 226.41,102.86 226.73,102.86 227.37,103.49 227.37,105.72 229.91,108.25 230.54,108.25 237.53,115.24 237.53,115.88 240.38,118.73 240.38,119.69 240.07,120 C10.J2
  Route15 0.254: v199.74,78.09 v202.6,75.24 | v206.41,75.24 207.68,76.5 208,76.19 208.63,76.19 216.57,84.13 216.25,84.44 216.25,87.94 v216.89,88.57
  Bottom 0.254: v130.53,109.21 142.28,109.21 142.91,109.84 152.44,109.84 153.39,110.8 C17.M2 | v129.89,76.82 130.21,76.5 150.21,76.5 v150.53,76.82 | v157.2,76.82 158.15,77.77 v165.77,77.77 | v173.71,76.82 173.71,78.09 174.34,78.73 199.11,78.73 v199.74,78.09 | v202.6,75.24 v206.41,75.24
N$109
  Bottom 0.254: C17.V1 157.83,89.21 158.79,90.16 234.67,90.16 235.62,89.21 239.11,89.21 C10.V2
N$111  (via drill 0.61)
  Top 0.254: v121,97.14 117.83,100.32 117.83,123.49 v118.15,123.81 | v131.8,141.59 132.12,141.91 132.12,150.48 131.48,151.12 130.53,151.12 130.53,173.66 131.48,174.61 v131.48,175.56 | v129.58,177.47 129.89,177.79 129.89,183.18 v129.58,183.5 | v154.98,183.5 155.29,183.82 v155.29,194.93 | v201.65,207 205.46,203.19 205.46,202.55 v207.05,200.96
  Route2 0.254: v131.48,175.56 v129.58,177.47 | v192.44,198.11 192.76,198.11 v201.65,207 | v211.49,201.6 211.49,202.24 213.71,204.46 215.62,204.46 217.84,202.24 220.06,204.46 224.19,204.46 226.41,206.68 226.41,209.86 v228.64,212.08 | v249.27,216.21 247.69,217.79 247.69,219.38 251.81,223.51 253.4,223.51 254.99,225.09 A09.U2
  Route15 0.254: v147.04,101.27 143.55,97.78 143.23,97.78 141.32,95.87 v141.64,95.55
  Bottom 0.254: v147.04,101.27 150.21,101.27 C17.R2 | v141.64,95.55 139.74,95.55 138.15,97.14 v121,97.14 | v118.15,123.81 114.02,127.94 114.02,141.59 124.5,141.59 125.13,142.23 127.35,142.23 127.99,141.59 v131.8,141.59 | v129.58,183.5 130.21,182.87 154.34,182.87 v154.98,183.5 | v155.29,194.93 155.93,195.57 160.37,195.57 162.91,198.11 166.72,198.11 169.26,195.57 170.85,195.57 171.49,196.2 173.71,196.2 175.61,198.11 184.19,198.11 184.82,197.47 187.68,197.47 188.31,198.11 v192.44,198.11 | v207.05,200.96 207.36,201.28 211.17,201.28 v211.49,201.6 | v228.64,212.08 228.95,212.39 238.16,212.39 238.8,211.76 245.46,211.76 249.27,215.57 v249.27,216.21
N$112  (via drill 0.61)
  Top 0.254: v253.08,155.88 254.04,156.83 v254.04,172.71 | v272.77,173.34 272.77,186.04 271.82,186.99 271.82,189.85 B08.F1
  Bottom 0.254: v253.08,155.88 254.99,155.88 B09.U2 | v254.04,172.71 254.67,173.34 v272.77,173.34
N$113  (via drill 0.61)
  Top 0.254: v265.47,181.28 266.42,182.23 266.42,186.36 265.15,187.63 B08.F2
  Bottom 0.254: v265.47,181.28 262.61,181.28 B09.K1
N$114  (via drill 0.61)
  Route15 0.254: v245.46,231.13 252.13,224.46 252.13,222.87 A09.V2
  Bottom 0.254: v245.46,231.13 243.56,233.03 231.81,233.03 230.86,232.08 A11.S2
N$115
  Bottom 0.254: C17.P2 154.66,105.08 155.61,106.03 171.17,106.03 173.07,107.94 C15.N2
N$116  (via drill 0.61)
  Top 0.254: v181.33,97.14 181.33,108.57 181.96,109.21 181.96,111.11 181.33,111.75 181.33,115.24 179.74,116.83 C15.K2
  Bottom 0.254: v181.33,97.14 203.24,97.14 204.19,98.1 C13.S2
N$117
  Top 0.254: D12.N2 214.98,38.4 217.21,40.63 D12.M2 217.21,41.9 217.21,44.44 215.94,45.71 215.94,70.16 215.3,70.79 215.3,74.6 215.62,74.92 215.62,112.38 216.25,113.02 216.25,118.1 217.52,119.37 C12.H2
N$118  (via drill 0.61)
  Top 0.254: v210.54,81.27 210.22,80.95 210.22,73.97 209.9,73.65 209.9,65.08 210.54,64.44 210.54,61.58 209.27,60.31 209.27,45.07 v209.59,44.75 | v230.22,115.56 C11.K2
  Route2 0.254: v230.22,115.56 230.22,114.29 229.27,113.33 229.27,112.07 225.78,108.57 225.78,104.44 225.46,104.13 225.46,102.86 220.7,98.1 220.7,97.14 216.25,92.7 216.25,89.21 215.94,88.89 215.94,86.35 v214.35,84.76
  Bottom 0.254: D12.K2 217.21,46.98 214.98,44.75 D12.L2 213.71,44.75 v209.59,44.75 | v214.35,84.76 210.86,81.27 v210.54,81.27
N$119  (via drill 0.61)
  Top 0.254: v180.69,126.67 181.33,126.03 181.33,117.46 184.19,114.61 v184.19,111.43 | v207.68,112.38 206.73,111.43 206.73,106.03 v207.05,105.72
  Bottom 0.254: v180.69,126.67 176.88,126.67 C15.F2 | v184.19,111.43 185.14,112.38 v207.68,112.38 | v207.05,105.72 206.41,105.08 205.46,105.08 C13.P2
N$123
  Top 0.254: A18.J2 137.83,254.62 136.88,255.58 136.88,262.56 137.83,263.51 137.83,266.05 A18.D2
  Bottom 0.254: AB19.AF2 126.08,260.66 127.04,261.61 129.89,261.61 134.66,266.37 137.51,266.37 A18.D2
N$124  (via drill 0.61)
  Top 0.254: v236.89,266.05 236.89,269.23 A11.C1 | v247.69,265.74 248,265.42 248,233.35 248.96,232.4 A10.S1
  Bottom 0.254: v236.89,266.05 238.48,266.05 239.11,265.42 247.37,265.42 v247.69,265.74
N$125  (via drill 0.61)
  Route2 0.254: v251.81,243.51 258.48,250.18 259.43,250.18 261.34,248.27 261.66,248.59 262.29,248.59 268.01,242.87 271.82,242.87 274.04,240.65 273.72,240.33 273.72,239.38 274.36,238.75 A08.P1
  Bottom 0.254: v251.81,243.51 250.86,242.56 247.69,242.56 246.73,241.61 A10.N1
N$126
  Top 0.254: A18.E2 141.64,262.88 141.96,262.56 141.96,258.43 142.59,257.8 142.59,252.72 141.64,251.77 141.64,251.45 A18.K2
  Bottom 0.254: AB19.AH2 129.26,256.85 130.85,255.26 132.75,255.26 134.66,253.35 135.29,253.35 137.51,251.13 140.69,251.13 A18.K2
N$127  (via drill 0.61)
  Top 0.254: B18.J2 137.83,184.77 136.88,185.73 136.88,195.25 137.83,196.2 B18.D2 | v125.77,193.98 123.54,196.2 123.54,204.46 123.86,204.77 123.86,215.25 123.54,215.57 123.54,239.06 125.13,240.65 AB19.AN2
  Bottom 0.254: v125.77,193.98 127.04,192.71 127.67,192.71 128.31,192.08 130.53,192.08 131.48,193.03 132.43,193.03 135.93,196.52 137.51,196.52 B18.D2
N$128  (via drill 0.61)
  Top 0.254: v262.93,253.04 263.24,252.72 263.24,245.1 v263.56,244.78 | v227.05,270.81 A11.D2
  Route2 0.254: v263.56,244.78 266.74,241.61 267.05,241.92 268.32,241.92 268.64,242.24 270.23,242.24 270.86,241.61 A08.N1
  Route15 0.254: v233.72,270.81 239.11,265.42 241.97,265.42 242.61,264.78 243.56,264.78 245.78,262.56 248.32,262.56 249.91,260.97 249.91,260.34 253.4,256.85 253.4,255.89 257.85,251.45 258.48,251.45 261.34,254.3 262.61,253.04 v262.93,253.04
  Bottom 0.254: v227.05,270.81 227.68,271.45 232.13,271.45 232.76,270.81 v233.72,270.81
N$129
  Bottom 0.254: C09.U2 256.26,91.74 257.85,90.16 261.02,90.16 261.97,89.21 264.51,89.21 C08.V2
N$130  (via drill 0.61)
  Top 0.254: B18.K2 141.01,181.6 140.69,181.92 140.69,186.04 140.05,186.68 140.05,188.9 141.01,189.85 141.01,193.03 B18.E2 141.01,194.3 141.01,198.11 139.74,199.38 139.74,203.51 139.1,204.14 139.1,207 139.42,207.31 v139.42,236.21
  Bottom 0.254: v139.42,236.21 130.21,236.21 128.94,237.48 AB19.AP2
N$131  (via drill 0.61)
  Top 0.254: A20.D2 112.43,266.05 111.48,265.1 111.48,255.58 112.43,254.62 A20.J2 112.43,253.35 110.84,251.77 110.84,221.6 v110.53,221.29
  Bottom 0.254: v110.53,221.29 110.84,220.97 121,220.97 122.27,222.24 AB19.AV2
N$132
  Bottom 0.254: A08.K1 274.04,251.13 272.45,252.72 269.59,252.72 265.78,256.53 265.15,256.53 260.07,261.61 241.34,261.61 239.75,263.19 237.21,263.19 A11.E1
N$133  (via drill 0.61)
  Top 0.254: 117.19,252.4 116.24,251.45 A20.K2 | 117.19,252.4 117.19,261.93 116.24,262.88 A20.E2 | v124.5,224.46 124.18,224.14 124.18,221.6 124.5,221.29 124.5,204.46 124.18,204.14 124.18,198.43 125.13,197.47 AB19.BD2 | v119.42,225.09 117.19,227.32 117.19,252.4
  Bottom 0.254: v124.5,224.46 124.18,224.14 120.37,224.14 v119.42,225.09
N$134
  Top 0.254: B20.J2 112.43,184.77 111.48,185.73 111.48,195.25 112.43,196.2 B20.D2
  Bottom 0.254: AB19.BH2 127.99,186.99 127.04,186.04 119.73,186.04 119.1,185.41 114.34,185.41 113.38,184.46 B20.J2
N$135
  Top 0.254: B20.E2 115.61,193.03 115.29,192.71 115.29,188.58 114.65,187.95 114.65,182.55 115.61,181.6 B20.K2
  Bottom 0.254: B20.K2 116.56,181.28 119.73,181.28 122.27,183.82 124.81,183.82 AB19.BJ2
N$136  (via drill 0.61)
  Top 0.254: A21.J2 99.73,254.62 98.78,255.58 98.78,265.1 99.73,266.05 A21.D2 | v119.42,174.93 117.83,176.52 117.83,181.6 118.15,181.92 118.15,183.18 117.83,183.5 v117.83,194.93 | v94.02,198.74 92.43,200.33 92.43,203.82 92.75,204.14 92.75,221.29 92.43,221.6 92.43,242.24 v94.02,243.83 | v99.73,243.19 101.32,244.78 v101.32,250.49 | v125.45,173.66 AB19.BN2
  Bottom 0.254: v125.45,173.66 125.13,173.34 121,173.34 v119.42,174.93 | v117.83,194.93 97.83,194.93 v94.02,198.74 | v94.02,243.83 94.33,243.51 95.92,243.51 96.24,243.19 v99.73,243.19 | v101.32,250.49 101.32,253.35 100.37,253.35 A21.J2
N$137  (via drill 0.61)
  Top 0.254: v241.34,268.28 241.34,264.15 238.48,261.29 238.48,223.83 239.43,222.87 A10.V2
  Bottom 0.254: v241.34,268.28 241.02,267.96 238.16,267.96 237.21,267 234.03,267 A11.D1
N$138  (via drill 0.61)
  Top 0.254: v243.56,229.22 243.56,226.36 243.24,226.05 A10.U2
  Bottom 0.254: v243.56,229.22 244.51,230.18 260.07,230.18 261.34,231.45 A09.S1
N$139
  Top 0.254: A10.T2 240.38,228.9 242.61,231.13 A10.S2
N$140  (via drill 0.61)
  Top 0.254: A21.E2 102.91,262.88 101.95,261.93 101.95,256.53 102.59,255.89 102.59,251.77 102.91,251.45 A21.K2 103.54,250.18 103.54,247 104.49,246.05 104.49,241.29 107.67,238.11 v107.67,226.05 | v127.67,165.4 127.67,166.99 128.31,167.63 AB19.BP2 | v101.64,165.4 101.32,165.72 101.32,200.33 101.95,200.96 v101.95,201.28 | v100.05,201.28 98.46,202.87 98.46,205.09 99.41,206.05 v99.41,210.17 | v97.51,212.08 96.56,213.03 v96.56,221.29
  Bottom 0.254: v127.67,165.4 126.08,163.82 123.86,163.82 121.96,165.72 121.32,165.72 120.37,164.77 120.37,164.45 119.73,163.82 103.22,163.82 v101.64,165.4 | v101.95,201.28 v100.05,201.28 | v99.41,210.17 v97.51,212.08 | v96.56,221.29 99.41,224.14 105.45,224.14 107.35,226.05 v107.67,226.05
N$142
  Bottom 0.254: C09.R1 259.43,101.91 261.02,103.49 266.74,103.49 267.69,104.44 C08.P2
N$146
  Bottom 0.254: C09.D1 259.43,133.02 260.7,131.75 263.88,131.75 264.2,131.43 269.91,131.43 270.86,130.48 274.04,130.48 C08.E1
N$147  (via drill 0.61)
  Top 0.254: v252.77,122.22 252.77,126.35 C09.F2 | v272.45,122.22 272.77,121.91 272.77,115.88 271.82,114.92 C08.L1
  Bottom 0.254: v252.77,122.22 253.08,121.91 263.88,121.91 265.15,123.18 265.78,123.18 266.74,122.22 v272.45,122.22
N$148  (via drill 0.61)
  Top 0.254: v272.77,112.38 272.77,100.63 274.36,99.05 C08.S1 | v262.29,113.02 262.29,116.83 C09.K1
  Bottom 0.254: v272.77,112.38 262.93,112.38 v262.29,113.02
N$150
  Bottom 0.254: D16.S2 167.36,28.25 172.44,28.25 D16.S1
N$151
  Top 0.254: D16.V2 163.87,19.67 164.82,20.62 164.82,30.15 163.87,31.1 D16.R2
N$153
  Top 0.254: A10.J2 239.43,254.62 239.43,259.7 A10.F2
N$155  (via drill 0.61)
  Top 0.254: v192.44,126.03 192.44,129.53 C14.E2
